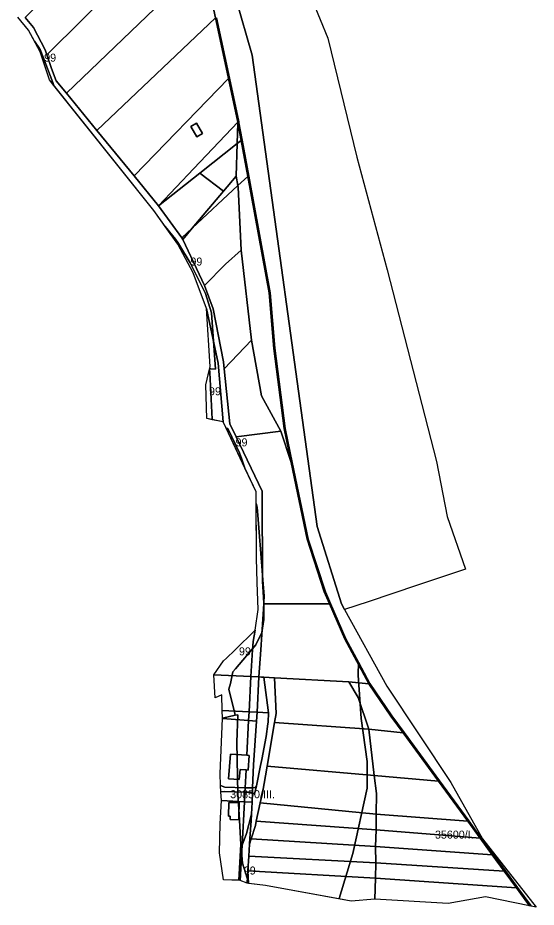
# Model space of a CAD drawing. Extents: x -535894 to -532834, y -1165802 to -1163645.
# Drawn here: x -533158 to -532834, y -1165802 to -1165247 of the extents above; entities that cross this region are included whole.
import ezdxf

# ---------------------------------------------------------------- set-up
doc = ezdxf.new("R2010")
doc.units = 0
for name, color, linetype in [('95610013', 7, 'Continuous'), ('95630013', 7, 'Continuous'), ('95640013', 7, 'Continuous'), ('95660013', 7, 'Continuous')]:
    doc.layers.add(name, color=color, linetype=linetype)

msp = doc.modelspace()

# ---------------------------------------------------------------- linework, layer by layer
at = {"layer": '95610013'}
for points in [[(-533055.7, -1165149.58), (-533052.58, -1165165.52), (-533049.49, -1165180.28), (-533139.66, -1165269.87), (-533140.71, -1165266.61), (-533148.1, -1165252.82), (-533153.35, -1165246.57)], [(-533049.49, -1165180.28), (-533041.97, -1165211.69), (-533127.5, -1165293.84), (-533133.87, -1165286.06), (-533136.9, -1165278.38), (-533139.66, -1165269.87)], [(-533041.97, -1165211.69), (-533040.38, -1165218.35), (-533034.31, -1165246.78), (-533108.53, -1165316.98), (-533127.5, -1165293.84)], [(-533026.24, -1165284.54), (-533085.21, -1165345.43), (-533108.53, -1165316.98), (-533034.31, -1165246.78)], [(-533020.4, -1165311.8), (-533047.82, -1165340.75), (-533069.91, -1165364.08), (-533085.21, -1165345.43), (-533026.24, -1165284.54)], [(-533020.29, -1165312.45), (-533020.71, -1165325.23), (-533044.05, -1165343.66), (-533069.91, -1165364.08), (-533047.82, -1165340.75), (-533020.4, -1165311.8)], [(-533049.68, -1165314.54), (-533045.93, -1165321.02), (-533042.47, -1165319.02), (-533046.22, -1165312.53)], [(-533018.3, -1165323.32), (-533020.71, -1165325.23), (-533020.29, -1165312.45)], [(-533018.3, -1165323.32), (-533014.2, -1165345.74), (-533020.29, -1165351.41), (-533021.4, -1165345.66), (-533020.71, -1165325.23)], [(-533020.71, -1165325.23), (-533021.4, -1165345.66), (-533029.31, -1165355), (-533044.05, -1165343.66)], [(-533020.29, -1165351.41), (-533048.83, -1165378), (-533029.31, -1165355), (-533021.4, -1165345.66)], [(-533020.29, -1165351.41), (-533014.2, -1165345.74), (-533000.89, -1165418.54), (-532997.81, -1165453.19), (-532991.41, -1165503.26), (-532986.99, -1165524.47), (-532993.56, -1165504.76), (-533005.56, -1165482.73), (-533011.83, -1165447.98), (-533018.33, -1165391.89), (-533020.07, -1165352.56)], [(-533020.07, -1165352.56), (-533018.33, -1165391.89), (-533028.16, -1165400.59), (-533041.17, -1165413.85), (-533054.81, -1165385.05), (-533048.83, -1165378), (-533020.29, -1165351.41)], [(-533055.45, -1165384.16), (-533048.83, -1165378), (-533054.81, -1165385.05)], [(-533018.33, -1165391.89), (-533011.83, -1165447.98), (-533028.93, -1165465.91), (-533029.4, -1165461.46), (-533035.8, -1165428.41), (-533041.17, -1165413.85), (-533028.16, -1165400.59)], [(-533032.72, -1165462.3), (-533029.56, -1165499.09), (-533039.75, -1165496.98), (-533040.44, -1165475.96), (-533037.58, -1165464.39), (-533039.93, -1165428.22)], [(-533011.83, -1165447.98), (-533005.56, -1165482.73), (-532993.56, -1165504.76), (-533021.44, -1165508.35), (-533025.3, -1165500.3), (-533028.93, -1165465.91)], [(-532993.56, -1165504.76), (-532986.99, -1165524.47), (-532977.01, -1165572.37), (-532966.34, -1165605.24), (-532963.13, -1165612.63), (-532990.62, -1165612.65), (-533004.15, -1165612.67), (-533004.39, -1165608.49), (-533004.95, -1165598.83), (-533005.12, -1165542.35), (-533021.44, -1165508.35)], [(-532990.62, -1165612.65), (-532963.13, -1165612.63), (-532953.54, -1165634.66), (-532938.47, -1165662.64), (-532951, -1165661.3), (-532997.56, -1165658.85), (-533004.03, -1165658.51), (-533005.63, -1165658.42), (-533007.17, -1165658.34), (-533006.05, -1165641.45), (-533004.15, -1165612.67)], [(-533009.63, -1165629.23), (-533010.83, -1165636.13), (-533011.2, -1165641.49), (-533012.33, -1165658.17), (-533035.33, -1165657.07), (-533029.26, -1165648.36), (-533027.52, -1165646.64), (-533022.33, -1165641.59)], [(-533035.33, -1165657.07), (-533012.33, -1165658.17), (-533013.39, -1165680.14), (-533030.17, -1165679.38), (-533030.42, -1165669.49), (-533034.47, -1165671.41)], [(-532997.56, -1165658.85), (-532996.45, -1165681.15), (-532997.44, -1165686.82), (-533002.12, -1165713.97), (-533005.03, -1165730.85), (-533006.36, -1165737.02), (-533008.83, -1165748.52), (-533009.41, -1165751.23), (-533011.98, -1165759.36), (-533013.08, -1165762.85), (-533012.84, -1165759.3), (-533012.14, -1165748.28), (-533011.87, -1165744.03), (-533011.45, -1165736.54), (-533011.24, -1165730.7), (-533009.87, -1165731.53), (-533008.79, -1165726.42), (-533006.19, -1165713.61), (-533005.43, -1165709.83), (-533002.65, -1165695.46), (-533001.54, -1165687.53), (-533001.5, -1165686.54), (-533001.3, -1165680.76), (-533004.03, -1165658.51)], [(-533005.63, -1165658.42), (-533004.03, -1165658.51), (-533001.3, -1165680.76), (-533008.34, -1165680.37), (-533007.17, -1165658.34)], [(-532951, -1165661.3), (-532945.26, -1165671.22), (-532938.52, -1165690.97), (-532997.44, -1165686.82), (-532996.45, -1165681.15), (-532997.56, -1165658.85)], [(-532951, -1165661.3), (-532938.47, -1165662.64), (-532924.76, -1165682.74), (-532917.12, -1165693.17), (-532938.52, -1165690.97), (-532945.26, -1165671.22)], [(-533013.39, -1165680.14), (-533013.66, -1165685.61), (-533030.05, -1165684.22), (-533030.17, -1165679.38)], [(-533030.05, -1165684.22), (-533013.66, -1165685.61), (-533014.78, -1165707.25), (-533025.05, -1165706.48), (-533026.17, -1165721.9), (-533019.55, -1165722.45), (-533019.02, -1165716.08), (-533015.26, -1165716.37), (-533015.84, -1165727.6), (-533028.54, -1165727.28), (-533031.13, -1165726.05), (-533031.47, -1165718.72)], [(-533001.3, -1165680.76), (-533001.5, -1165686.54), (-533001.54, -1165687.53), (-533002.65, -1165695.46), (-533005.43, -1165709.83), (-533006.19, -1165713.61), (-533008.79, -1165726.42), (-533009.72, -1165727.34), (-533011.13, -1165727.66), (-533010.61, -1165713.22), (-533008.65, -1165686.03), (-533008.34, -1165680.37)], [(-532997.44, -1165686.82), (-532938.52, -1165690.97), (-532935.09, -1165719.88), (-533002.12, -1165713.97)], [(-532938.52, -1165690.97), (-532917.12, -1165693.17), (-532895.01, -1165723.4), (-532935.09, -1165719.88)], [(-533002.12, -1165713.97), (-532935.09, -1165719.88), (-532933.75, -1165731.04), (-532933.84, -1165743.96), (-533006.36, -1165737.02), (-533005.03, -1165730.85)], [(-532935.09, -1165719.88), (-532895.01, -1165723.4), (-532876.69, -1165748.46), (-532933.84, -1165743.96), (-532933.75, -1165731.04)], [(-533031.13, -1165726.05), (-533028.54, -1165727.28), (-533015.84, -1165727.6), (-533015.98, -1165730.26), (-533028.61, -1165729.89), (-533030.94, -1165730.11)], [(-533008.79, -1165726.42), (-533009.87, -1165731.53), (-533011.24, -1165730.7), (-533011.13, -1165727.66), (-533009.72, -1165727.34)], [(-533028.61, -1165729.89), (-533015.98, -1165730.26), (-533016.29, -1165736.27), (-533030.69, -1165735.48), (-533030.94, -1165730.11)], [(-533030.69, -1165735.48), (-533016.29, -1165736.27), (-533017.76, -1165763.5), (-533018.93, -1165785.38), (-533029.32, -1165785.09), (-533031.86, -1165768.21), (-533031.38, -1165750.02)], [(-533026.09, -1165736.68), (-533026.27, -1165745.32), (-533025.22, -1165745.34), (-533025.26, -1165747.48), (-533019.83, -1165747.61), (-533019.76, -1165745.41), (-533019.61, -1165736.78)], [(-533006.36, -1165737.02), (-532933.84, -1165743.96), (-532933.91, -1165753.88), (-533008.83, -1165748.52)], [(-532933.84, -1165743.96), (-532876.69, -1165748.46), (-532868.89, -1165759.12), (-532933.91, -1165753.88)], [(-533008.83, -1165748.52), (-532933.91, -1165753.88), (-532934.37, -1165764.2), (-533011.98, -1165759.36), (-533009.41, -1165751.23)], [(-532933.91, -1165753.88), (-532868.89, -1165759.12), (-532861.38, -1165769.41), (-532934.37, -1165764.2)], [(-533011.98, -1165759.36), (-532934.37, -1165764.2), (-532934.06, -1165774.43), (-533013.56, -1165770.31), (-533013.08, -1165762.85)], [(-532934.37, -1165764.2), (-532861.38, -1165769.41), (-532853.86, -1165779.68), (-532934.06, -1165774.43)], [(-533013.56, -1165770.31), (-532934.06, -1165774.43), (-532934.35, -1165784.1), (-533014.15, -1165779.42)], [(-533014.15, -1165779.42), (-533013.8, -1165787.34), (-533014.65, -1165787.24)], [(-533014.15, -1165779.42), (-532934.35, -1165784.1), (-532934.73, -1165797.08), (-532949.49, -1165798.31), (-533003, -1165788.63), (-533013.8, -1165787.34)], [(-532934.06, -1165774.43), (-532853.86, -1165779.68), (-532846.26, -1165790.07), (-532934.35, -1165784.1)], [(-532934.35, -1165784.1), (-532846.26, -1165790.07), (-532838.03, -1165801.32), (-532865.54, -1165795.7), (-532888.93, -1165799.76), (-532934.73, -1165797.08)]]:
    msp.add_lwpolyline(points, close=True, dxfattribs=at)
at = {"layer": '95630013'}
msp.add_lwpolyline([(-532973.81, -1165236.01), (-532964.21, -1165259.48), (-532945.97, -1165333.71), (-532926.98, -1165404.07), (-532896.21, -1165523.88), (-532889.53, -1165558.14), (-532878.16, -1165591.08), (-532908.13, -1165601.07), (-532938.91, -1165611.34), (-532953.65, -1165616.26), (-532955.6, -1165612.74), (-532970.84, -1165564.38), (-533011.43, -1165270.01), (-533021.55, -1165234.47)], dxfattribs=at)
at = {"layer": '95640013'}
for points in [[(-533021.55, -1165234.47), (-533011.43, -1165270.01), (-532970.84, -1165564.38), (-532955.6, -1165612.74), (-532953.65, -1165616.26), (-532927.21, -1165664.12), (-532887.26, -1165724.36), (-532867.49, -1165759.55), (-532833.91, -1165802.16), (-532838.03, -1165801.32), (-532846.26, -1165790.07), (-532853.86, -1165779.68), (-532861.38, -1165769.41), (-532868.89, -1165759.12), (-532876.69, -1165748.46), (-532895.01, -1165723.4), (-532917.12, -1165693.17), (-532924.76, -1165682.74), (-532938.47, -1165662.64), (-532953.54, -1165634.66), (-532963.13, -1165612.63), (-532966.34, -1165605.24), (-532977.01, -1165572.37), (-532986.99, -1165524.47), (-532991.41, -1165503.26), (-532997.81, -1165453.19), (-533000.89, -1165418.54), (-533014.2, -1165345.74), (-533018.3, -1165323.32), (-533020.29, -1165312.45), (-533020.4, -1165311.8), (-533026.24, -1165284.54), (-533034.31, -1165246.78), (-533040.38, -1165218.35)], [(-533153.35, -1165246.57), (-533148.1, -1165252.82), (-533140.71, -1165266.61), (-533139.66, -1165269.87), (-533136.9, -1165278.38), (-533133.87, -1165286.06), (-533127.5, -1165293.84), (-533108.53, -1165316.98), (-533085.21, -1165345.43), (-533069.91, -1165364.08), (-533055.45, -1165384.16), (-533054.81, -1165385.05), (-533041.17, -1165413.85), (-533035.8, -1165428.41), (-533029.4, -1165461.46), (-533028.93, -1165465.91), (-533025.3, -1165500.3), (-533021.44, -1165508.35), (-533005.12, -1165542.35), (-533004.95, -1165598.83), (-533004.39, -1165608.49), (-533004.15, -1165612.67), (-533006.05, -1165641.45), (-533007.17, -1165658.34), (-533012.33, -1165658.17), (-533011.2, -1165641.49), (-533010.83, -1165636.13), (-533009.63, -1165629.23), (-533007.66, -1165616.19), (-533008.26, -1165599.32), (-533008.78, -1165584.18), (-533008.86, -1165542.74), (-533029.56, -1165499.09), (-533032.72, -1165462.3), (-533039.93, -1165428.22), (-533048.28, -1165406.03), (-533057.97, -1165388.13), (-533072.82, -1165367.05), (-533138.08, -1165285.36), (-533143.81, -1165267.88), (-533151.29, -1165254.43), (-533157.9, -1165246.26)]]:
    msp.add_lwpolyline(points, dxfattribs=at)
for points in [[(-533049.68, -1165314.54), (-533046.22, -1165312.53), (-533042.47, -1165319.02), (-533045.93, -1165321.02)], [(-533044.05, -1165343.66), (-533029.31, -1165355), (-533048.83, -1165378), (-533055.45, -1165384.16), (-533069.91, -1165364.08)], [(-533012.33, -1165658.17), (-533007.17, -1165658.34), (-533008.34, -1165680.37), (-533013.39, -1165680.14)], [(-533008.34, -1165680.37), (-533008.65, -1165686.03), (-533013.66, -1165685.61), (-533013.39, -1165680.14)], [(-533013.66, -1165685.61), (-533008.65, -1165686.03), (-533010.61, -1165713.22), (-533011.13, -1165727.66), (-533012.01, -1165727.69), (-533015.84, -1165727.6), (-533015.26, -1165716.37), (-533013.9, -1165716.47), (-533013.25, -1165707.37), (-533014.78, -1165707.25)], [(-533014.78, -1165707.25), (-533013.25, -1165707.37), (-533013.9, -1165716.47), (-533015.26, -1165716.37), (-533019.02, -1165716.08), (-533019.55, -1165722.45), (-533026.17, -1165721.9), (-533025.05, -1165706.48)], [(-533012.01, -1165727.69), (-533011.13, -1165727.66), (-533011.24, -1165730.7), (-533012.06, -1165730.37), (-533015.98, -1165730.26), (-533015.84, -1165727.6)], [(-533012.06, -1165730.37), (-533011.24, -1165730.7), (-533011.45, -1165736.54), (-533016.29, -1165736.27), (-533015.98, -1165730.26)], [(-533026.09, -1165736.68), (-533019.61, -1165736.78), (-533019.76, -1165745.41), (-533019.83, -1165747.61), (-533025.26, -1165747.48), (-533025.22, -1165745.34), (-533026.27, -1165745.32)], [(-533016.29, -1165736.27), (-533011.45, -1165736.54), (-533011.87, -1165744.03), (-533015, -1165756.19), (-533017.76, -1165763.5)], [(-533011.87, -1165744.03), (-533012.14, -1165748.28), (-533012.84, -1165759.3), (-533013.08, -1165762.85), (-533013.56, -1165770.31), (-533014.15, -1165779.42), (-533014.65, -1165787.24), (-533018.93, -1165785.38), (-533017.76, -1165763.5), (-533015, -1165756.19)]]:
    msp.add_lwpolyline(points, close=True, dxfattribs=at)
at = {"layer": '95660013'}
for points in [[(-532973.81, -1165236.01), (-532964.21, -1165259.48), (-532945.97, -1165333.71), (-532926.98, -1165404.07), (-532896.21, -1165523.88), (-532889.53, -1165558.14), (-532878.16, -1165591.08), (-532908.13, -1165601.07), (-532938.91, -1165611.34), (-532953.65, -1165616.26), (-532927.21, -1165664.12), (-532887.26, -1165724.36), (-532867.49, -1165759.55), (-532833.91, -1165802.16), (-532837.133, -1165801.503), (-532837.38, -1165801.168), (-532845.607, -1165789.921), (-532853.204, -1165779.528), (-532860.724, -1165769.255), (-532868.243, -1165758.971), (-532876.041, -1165748.305), (-532894.362, -1165723.248), (-532916.475, -1165693.021), (-532924.108, -1165682.584), (-532937.819, -1165662.486), (-532945.064, -1165649.039), (-532952.897, -1165634.501), (-532962.481, -1165612.478), (-532965.694, -1165605.088), (-532976.364, -1165572.211), (-532986.352, -1165524.318), (-532990.773, -1165503.102), (-532997.177, -1165453.032), (-533000.256, -1165418.383), (-533013.57, -1165345.583), (-533017.667, -1165323.165), (-533019.657, -1165312.29), (-533019.776, -1165311.643), (-533025.608, -1165284.384), (-533033.684, -1165246.624)], [(-533033.684, -1165246.624), (-533025.608, -1165284.384), (-533019.776, -1165311.643), (-533019.657, -1165312.29), (-533017.667, -1165323.165), (-533013.57, -1165345.583), (-533000.256, -1165418.383), (-532997.177, -1165453.032), (-532990.773, -1165503.102), (-532986.352, -1165524.318), (-532976.364, -1165572.211), (-532965.694, -1165605.088), (-532962.481, -1165612.478), (-532952.897, -1165634.501), (-532945.064, -1165649.039), (-532945.227, -1165657.244), (-532943.26, -1165684.34), (-532939.6, -1165711.26), (-532939.6, -1165727.83), (-532948.52, -1165768.6), (-532957.152, -1165796.648), (-532957.254, -1165796.905), (-533003, -1165788.63), (-533013.447, -1165787.382), (-533017.43, -1165774.62), (-533018.42, -1165762.8), (-533019.64, -1165744.17), (-533020.47, -1165731.41), (-533021.03, -1165699.01), (-533020.38, -1165682.03), (-533022.04, -1165682.32), (-533022.332, -1165681.09), (-533025.91, -1165666.02), (-533025.04, -1165662.36), (-533023.51, -1165655.23), (-533021.85, -1165653.29), (-533009.03, -1165638.23), (-533005.45, -1165630.68), (-533004.13, -1165622.47), (-533004.03, -1165611.58), (-533003.99, -1165607.59), (-533004.73, -1165597.84), (-533005.2, -1165591.78), (-533007.83, -1165557.29), (-533008.203, -1165552.363), (-533008.21, -1165552.27), (-533008.846, -1165550.096), (-533008.86, -1165542.74), (-533015.911, -1165527.873), (-533018.108, -1165521.731), (-533019.3, -1165518.4), (-533026.6, -1165503.27), (-533026.892, -1165503.208), (-533027.687, -1165503.04), (-533029.56, -1165499.09), (-533036.321, -1165497.69), (-533036.337, -1165497.392), (-533037.905, -1165468.116), (-533038.011, -1165466.134), (-533037.926, -1165465.79), (-533037.344, -1165465.843), (-533034.26, -1165466.13), (-533036.87, -1165430.9), (-533040.6, -1165418.9), (-533050.15, -1165399.71), (-533057.38, -1165387.57), (-533059.418, -1165385.017), (-533065.753, -1165377.081), (-533072.82, -1165367.05), (-533135.282, -1165288.862), (-533135.978, -1165287.047), (-533142.009, -1165271.315), (-533143.831, -1165266.563), (-533143.97, -1165266.2), (-533144.257, -1165265.797), (-533147.519, -1165261.21), (-533151.29, -1165254.43), (-533157.9, -1165246.26)]]:
    msp.add_lwpolyline(points, dxfattribs=at)
for points in [[(-533135.978, -1165287.047), (-533135.282, -1165288.862), (-533138.08, -1165285.36), (-533143.81, -1165267.88), (-533147.519, -1165261.21), (-533144.257, -1165265.797), (-533143.97, -1165266.2), (-533143.831, -1165266.563), (-533142.009, -1165271.315)], [(-533036.87, -1165430.9), (-533034.26, -1165466.13), (-533037.344, -1165465.843), (-533037.926, -1165465.79), (-533037.58, -1165464.39), (-533039.93, -1165428.22), (-533048.28, -1165406.03), (-533057.97, -1165388.13), (-533065.753, -1165377.081), (-533059.418, -1165385.017), (-533057.38, -1165387.57), (-533050.15, -1165399.71), (-533040.6, -1165418.9)], [(-533036.337, -1165497.392), (-533036.321, -1165497.69), (-533039.75, -1165496.98), (-533040.44, -1165475.96), (-533038.011, -1165466.134), (-533037.905, -1165468.116)], [(-533018.108, -1165521.731), (-533015.911, -1165527.873), (-533027.687, -1165503.04), (-533026.892, -1165503.208), (-533026.6, -1165503.27), (-533019.3, -1165518.4)], [(-533025.91, -1165666.02), (-533022.332, -1165681.09), (-533022.04, -1165682.32), (-533030.055, -1165684.016), (-533030.17, -1165679.38), (-533030.42, -1165669.49), (-533034.47, -1165671.41), (-533035.33, -1165657.07), (-533029.26, -1165648.36), (-533027.52, -1165646.64), (-533022.33, -1165641.59), (-533009.63, -1165629.23), (-533007.66, -1165616.19), (-533008.26, -1165599.32), (-533008.78, -1165584.18), (-533008.846, -1165550.096), (-533008.21, -1165552.27), (-533008.203, -1165552.363), (-533007.83, -1165557.29), (-533005.2, -1165591.78), (-533004.73, -1165597.84), (-533003.99, -1165607.59), (-533004.03, -1165611.58), (-533004.13, -1165622.47), (-533005.45, -1165630.68), (-533009.03, -1165638.23), (-533021.85, -1165653.29), (-533023.51, -1165655.23), (-533025.04, -1165662.36)], [(-532837.133, -1165801.503), (-532838.03, -1165801.32), (-532865.54, -1165795.7), (-532888.93, -1165799.76), (-532934.73, -1165797.08), (-532949.49, -1165798.31), (-532957.254, -1165796.905), (-532957.152, -1165796.648), (-532948.52, -1165768.6), (-532939.6, -1165727.83), (-532939.6, -1165711.26), (-532943.26, -1165684.34), (-532945.227, -1165657.244), (-532945.064, -1165649.039), (-532937.819, -1165662.486), (-532924.108, -1165682.584), (-532916.475, -1165693.021), (-532894.362, -1165723.248), (-532876.041, -1165748.305), (-532868.243, -1165758.971), (-532860.724, -1165769.255), (-532853.204, -1165779.528), (-532845.607, -1165789.921), (-532837.38, -1165801.168)], [(-533018.42, -1165762.8), (-533019.857, -1165785.354), (-533029.32, -1165785.09), (-533031.86, -1165768.21), (-533031.38, -1165750.02), (-533030.69, -1165735.48), (-533030.94, -1165730.11), (-533031.13, -1165726.05), (-533031.47, -1165718.72), (-533030.05, -1165684.22), (-533030.055, -1165684.016), (-533022.04, -1165682.32), (-533020.38, -1165682.03), (-533021.03, -1165699.01), (-533020.47, -1165731.41), (-533019.64, -1165744.17)], [(-533017.43, -1165774.62), (-533013.447, -1165787.382), (-533013.8, -1165787.34), (-533014.65, -1165787.24), (-533018.93, -1165785.38), (-533019.857, -1165785.354), (-533018.42, -1165762.8)]]:
    msp.add_lwpolyline(points, close=True, dxfattribs=at)

# ---------------------------------------------------------------- texts
for s, rotation, p in [('99', 0, (-533141.401, -1165274.066)), ('99', 0, (-533050.007, -1165401.42)), ('99', 360, (-533038.38, -1165482.446)), ('99', 0, (-533021.799, -1165514.339)), ('99', 360, (-533019.66, -1165644.854)), ('30850/III.', 360, (-533025.14, -1165734.091)), ('35600/I.', 360, (-532897.194, -1165759.327)), ('99', 360, (-533016.652, -1165781.741))]:
    msp.add_text(s, height=5, rotation=rotation, dxfattribs=at).set_placement(p)

doc.saveas('drawing.dxf')
